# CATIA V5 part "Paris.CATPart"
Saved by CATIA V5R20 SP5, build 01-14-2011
Part number: 巴黎圣母院
Bounding box of the stored display mesh (mm): x -142 to 142, y -290 to 12, z 0 to 410
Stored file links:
  E:\180131213何浏楠\Paris.CATPart
  C:\Program Files\Dassault Systemes\B20\intel_a\startup\materials\Catalog.CATMaterial
  C:\Program Files\Dassault Systemes\B20\intel_a\startup\materials\marble_3.jpg
  C:\Program Files\Dassault Systemes\B20\intel_a\startup\materials\brushed_metal2.jpg
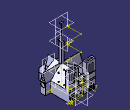
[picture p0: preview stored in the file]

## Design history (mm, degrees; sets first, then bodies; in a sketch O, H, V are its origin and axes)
Body1 (main body)
  Sketch1 on xy-plane, origin (0, 0, 0), H (1, 0, 0), V (0, 1, 0)
    line L1 (-100, -20) -> (100, -20)
    line L2 (100, -20) -> (100, 10)
    line L3 (100, 10) -> (-100, 10)
    line L4 (-100, 10) -> (-100, -20)
    horizontal: L1 H, L3 H
    vertical: L2 V, L4 V
  Pad1: profile Sketch1, direction (0, 0, 1), length 80
  Sketch2 on xy-plane, origin (0, 0, 0), H (1, 0, 0), V (0, 1, 0)
    line L1 (-100, 10) -> (-30, 10)
    line L2 (-30, 10) -> (-30, -20)
    line L3 (-30, -20) -> (-100, -20)
    line L4 (-100, -20) -> (-100, 10)
    point P5 (30, 10)
    line L5 (30, 10) -> (100, 10)
    line L6 (100, 10) -> (100, -20)
    line L7 (100, -20) -> (30, -20)
    line L8 (30, -20) -> (30, 10)
    horizontal: L1 H, L3 H, L5 H, L7 H
    vertical: L2 V, L4 V, L6 V, L8 V
    coincidence: P5 L1
  Pad2: profile Sketch2, direction (0, 0, 1), length 200
  Plane1: type Offset, RefPlane xy-plane, Offset 80
  Sketch3 on Plane1, origin (0, 0, 80), H (1, 0, 0), V (0, 1, 0)
    line L1 (-20, 0) -> (20, 0)
    point P1 (-20, 0)
    coincidence: P1 H
    horizontal: L1 H
  Plane2: type Angle, RefPlane Plane1, Direction Sketch3, Angle 90
  Sketch4 on Plane2, origin (0, 0, 0), H (1, 0, 0), V (0, 0, 1)
    line L1 (-100, 80) -> (100, 80)
    line L2 (100, 80) -> (100, 0)
    line L3 (100, 0) -> (-100, 0)
    line L4 (-100, 0) -> (-100, 80)
    horizontal: L1 H, L3 H
    vertical: L2 V, L4 V
  Pad3: profile Sketch4, direction (0, -1, 0), length 200
  Plane3: type Offset, RefPlane Plane2, Offset 150
  Sketch5 on Plane3, origin (0, -150, 0), H (1, 0, 0), V (0, 0, 1)
    line L1 (-20, 80) -> (20, 80)
    horizontal: L1 H
  Plane4: type Angle, RefPlane Plane3, Direction Sketch5, Angle 90
  Plane5: type Offset, RefPlane Plane4, Offset 80
  Sketch6 on Plane4, origin (0, 0, 80), H (1, 0, 0), V (0, -1, 0)
    point P1 (0, 150)
    line L1 (10, 160) -> (10, 140)
    line L2 (10, 140) -> (-10, 140)
    line L3 (-10, 140) -> (-10, 160)
    line L4 (-10, 160) -> (10, 160)
    coincidence: P1 V
    vertical: L1 V, L3 V
    horizontal: L2 H, L4 H
    equidistance: L1 L3 P1, L2 L4 P1
  Pad4: profile Sketch6, direction (0, 0, 1), length 200
  Sketch7 on Plane2, origin (0, 0, 0), H (1, 0, 0), V (0, 0, 1)
    line L1 (-100, 80) -> (0, 140)
    line L2 (0, 140) -> (100, 80)
    line L3 (-100, 80) -> (100, 80)
    horizontal: L3 H
  Pad5: profile Sketch7, direction (0, -1, 0), length 200
  Plane6: type Offset, RefPlane Plane5, Offset 280, reversed
  Sketch8 on Plane5, origin (0, 0, 0), H (1, 0, 0), V (0, -1, 0)
    line L1 (-100, 170) -> (-140, 170)
    line L2 (-140, 170) -> (-140, 130)
    line L3 (-140, 130) -> (-100, 130)
    line L4 (-100, 130) -> (-100, 170)
    point P5 (100, 170)
    line L5 (100, 170) -> (140, 170)
    line L6 (140, 170) -> (140, 130)
    line L7 (140, 130) -> (100, 130)
    line L8 (100, 130) -> (100, 170)
    point P7 (140, 130)
    horizontal: L1 H, L3 H, L5 H, L7 H
    vertical: L2 V, L4 V, L6 V, L8 V
    coincidence: P5 L1, P7 L3
  Pad6: profile Sketch8, direction (0, 0, 1), length 80
  Sketch9 on Plane5, origin (0, 0, 0), H (1, 0, 0), V (0, -1, 0)
    line L1 (0, 170) -> (0, 130)
    point P1 (0, 170)
    coincidence: P1 V
    vertical: L1 V
  Plane7: type Angle, RefPlane Plane5, Direction Sketch9, Angle 90
  Plane8: type Offset, RefPlane Plane7, Offset 140
  Sketch10 on Plane8, origin (-140, 0, 0), H (0, -1, 0), V (0, 0, 1)
    line L1 (130, 80) -> (150, 140)
    line L2 (150, 140) -> (170, 80)
    line L3 (130, 80) -> (170, 80)
    horizontal: L3 H
  Pad7: profile Sketch10, direction (1, 0, 0), length 280
  Sketch11 on Plane5, origin (0, 0, 0), H (1, 0, 0), V (0, -1, 0)
    line L1 (-20, 200) -> (20, 200)
    line L2 (20, 200) -> (20, 250)
    line L3 (-20, 250) -> (-20, 200)
    arc A1 centre (0, 250) radius 20 from (20, 250) to (-20, 250) ccw
    horizontal: L1 H
    vertical: L2 V, L3 V
    tangency: A1 L2
  Pad8: profile Sketch11, direction (0, 0, 1), length 80
  Sketch12 on Plane3, origin (0, -150, 0), H (1, 0, 0), V (0, 0, 1)
    line L1 (-20, 80) -> (0, 140)
    line L2 (0, 140) -> (20, 80)
    line L3 (-20, 80) -> (20, 80)
    horizontal: L3 H
  Pad9: profile Sketch12, direction (0, -1, 0), length 100
  Plane9: type Offset, RefPlane Plane3, Offset 100
  Sketch13 on Plane9, origin (0, -250, 0), H (1, 0, 0), V (0, 0, 1)
    point P1 (0, 140)
    line L1 (0, 140) -> (-20.024, 80.008)
    line L2 (-20.024, 80.008) -> (-0.9799, 80.008)
    line L3 (-0.9799, 80.008) -> (0, 140)
    axis line L4 (0, 145.4942) -> (0, 57.6388)
    point P4 (0, 145.4942)
    length L1 = 63.2456
    length L3 = 60
    coincidence: P1 V, P4 V
    horizontal: L2 H
    vertical: L4 V
  Shaft1: profile Sketch13, axis Sketch13.L4, angle 180
  Sketch14 on Plane6, origin (0, 0, 280), H (1, 0, 0), V (0, -1, 0)
    line L1 (0, 129.2513) -> (0, 170.6804)
    point P1 (0, 129.2513)
    coincidence: P1 V
    vertical: L1 V
  Plane10: type Angle, RefPlane Plane6, Direction Sketch14, Angle 90
  Sketch15 on Plane10, origin (0, 0, 0), H (0, 1, 0), V (0, 0, 1)
    line L1 (-150, 280) -> (-140, 280)
    line L2 (-140, 280) -> (-150, 400)
    line L3 (-150, 400) -> (-150, 280)
    horizontal: L1 H
    vertical: L3 V
  Shaft2: profile Sketch15, axis Sketch15.L3, angle 360
  Plane11: type Offset, RefPlane Plane2, Offset 10, reversed
  Sketch16 on Plane11, origin (0, 10, 0), H (1, 0, 0), V (0, 0, 1)
    line L1 (80, 120) -> (70, 120)
    line L2 (70, 120) -> (70, 180)
    line L3 (70, 180) -> (80, 180)
    line L4 (80, 180) -> (80, 120)
    point P5 (60, 120)
    line L5 (60, 120) -> (50, 120)
    line L6 (50, 120) -> (50, 180)
    line L7 (50, 180) -> (60, 180)
    line L8 (60, 180) -> (60, 120)
    point P7 (50, 180)
    line L9 (-50, 120) -> (-60, 120)
    line L10 (-60, 120) -> (-60, 180)
    line L11 (-60, 180) -> (-50, 180)
    line L12 (-50, 180) -> (-50, 120)
    point P11 (-60, 180)
    point P13 (-70, 120)
    line L13 (-70, 120) -> (-80, 120)
    line L14 (-80, 120) -> (-80, 180)
    line L15 (-80, 180) -> (-70, 180)
    line L16 (-70, 180) -> (-70, 120)
    point P15 (-80, 180)
    horizontal: L1 H, L3 H, L5 H, L7 H, L9 H, L11 H, L13 H, L15 H
    vertical: L2 V, L4 V, L6 V, L8 V, L10 V, L12 V, L14 V, L16 V
    coincidence: P5 L1, P7 L3, P11 L3, P13 L1, P15 L3
  Pocket1: profile Sketch16, direction (0, -1, 0), length 10
  Sketch17 on Plane11, origin (0, 10, 0), H (1, 0, 0), V (0, 0, 1)
    line L1 (100, 80) -> (-100, 80)
    line L2 (-100, 80) -> (-100, 70)
    line L3 (-100, 70) -> (100, 70)
    line L4 (100, 70) -> (100, 80)
    horizontal: L1 H, L3 H
    vertical: L2 V, L4 V
  Pad10: profile Sketch17, direction (0, 1, 0), length 2
  Sketch18 on Plane11, origin (0, 10, 0), H (1, 0, 0), V (0, 0, 1)
    point P1 (90, 0)
    line L1 (90, 0) -> (90, 30)
    point P2 (90, 30)
    point P3 (50, 30)
    line L2 (50, 30) -> (50, 0)
    line L3 (50, 0) -> (90, 0)
    spline S1 through (90, 30) (70, 50) (50, 30)
    point P5 (40, 0)
    line L4 (40, 0) -> (-40, 0)
    line L5 (-40, 0) -> (-40, 40)
    line L6 (40, 40) -> (40, 0)
    point P7 (-40, 40)
    point P8 (40, 40)
    spline S2 through (40, 40) (0, 60) (-40, 40)
    line L7 (-50, 0) -> (-90, 0)
    line L8 (-90, 0) -> (-90, 30)
    line L9 (-50, 30) -> (-50, 0)
    point P11 (-90, 30)
    point P12 (-50, 30)
    spline S3 through (-50, 30) (-70, 50) (-90, 30)
    point P13 (90, 30)
    point P14 (50, 30)
    point P15 (40, 40)
    point P16 (0, 60)
    point P17 (-40, 40)
    point P18 (-50, 30)
    point P19 (-90, 30)
    coincidence: P1 H, P13 P2, P14 P3, P5 H, P15 P8, P16 V, P17 P7, P18 P12, P19 P11
    vertical: L1 V, L2 V, L5 V, L6 V, L8 V, L9 V
    horizontal: L3 H, L4 H, L7 H
  Pocket2: profile Sketch18, direction (0, -1, 0), length 5
  Sketch19 on Plane11, origin (0, 10, 0), H (1, 0, 0), V (0, 0, 1)
    line L1 (13.6707, 40) -> (5, 40)
    line L2 (5, 40) -> (5, 0)
    line L3 (5, 0) -> (13.6707, 0)
    line L4 (13.6707, 0) -> (13.6707, 40)
    point P5 (-5, 40)
    line L5 (-5, 40) -> (-14.8635, 40)
    line L6 (-14.8635, 40) -> (-14.8635, 0)
    line L7 (-14.8635, 0) -> (-5, 0)
    line L8 (-5, 0) -> (-5, 40)
    distance L2 V = 5
    length L4 = 40
    distance L3 H = 0
    length L6 = 40
    distance V L8 = 5
    horizontal: L1 H, L3 H, L5 H, L7 H
    vertical: L2 V, L4 V, L6 V, L8 V
    coincidence: P5 L1
  Pocket3: profile Sketch19, direction (0, -1, 0), length 15
  Sketch20 on zx-plane, origin (0, 0, 0), H (-1, 0, 0), V (0, 0, 1)
    construction line L1 (-70, 40) -> (-70, -30)
    axis line L2 (70, 40) -> (70, -30)
    line L3 (-80, 30) -> (-73, 30)
    line L4 (-73, 30) -> (-73, 0)
    line L5 (-73, 0) -> (-80, 0)
    line L6 (-80, 0) -> (-80, 30)
    point P7 (-73, 0)
    point P9 (-67, 30)
    line L7 (-67, 30) -> (-60, 30)
    line L8 (-60, 30) -> (-60, 0)
    line L9 (-60, 0) -> (-67, 0)
    line L10 (-67, 0) -> (-67, 30)
    point P11 (-60, 0)
    point P13 (60, 30)
    line L11 (60, 30) -> (67, 30)
    line L12 (67, 30) -> (67, 0)
    line L13 (67, 0) -> (60, 0)
    line L14 (60, 0) -> (60, 30)
    point P15 (67, 0)
    point P17 (80, 30)
    line L15 (80, 30) -> (73, 30)
    line L16 (73, 30) -> (73, 0)
    line L17 (73, 0) -> (80, 0)
    line L18 (80, 0) -> (80, 30)
    point P19 (73, 0)
    distance L1 L4 = 3
    length L3 = 7
    length L9 = 7
    distance L10 L1 = 3
    distance L12 L2 = 3
    length L13 = 7
    length L17 = 7
    distance L18 L2 = 10
    vertical: L1 V, L2 V, L4 V, L6 V, L8 V, L10 V, L12 V, L14 V, L16 V, L18 V
    horizontal: L3 H, L5 H, L7 H, L9 H, L11 H, L13 H, L15 H, L17 H
    coincidence: P7 H, P9 L3, P11 H, P13 L3, P15 H, P17 L3, P19 H
  Pocket4: profile Sketch20, direction (0, -1, 0), length 6, mirrored extent
  Sketch21 on Plane11, origin (0, 10, 0), H (1, 0, 0), V (0, 0, 1)
    axis line L1 (100, 80.5911) -> (-100, 80.5911)
    horizontal: L1 H
  Sketch22 on face of Pad2, origin (0, 10, 0), H (-1, 0, 0), V (0, 0, 1)
    line L1 (-93.8519, 119) -> (-36.8149, 119)
    line L2 (-36.8149, 119) -> (-36.8149, 118)
    line L3 (-36.8149, 118) -> (-93.8519, 118)
    line L4 (-93.8519, 118) -> (-93.8519, 119)
    reference projected line E1 (-100, 80) -> (100, 80) from edge [end face of Pad10 | face of Pad10 from Sketch17.L1]
    point P5 (36.1818, 118)
    line L5 (36.1818, 118) -> (93.7227, 118)
    line L6 (93.7227, 118) -> (93.7227, 119)
    line L7 (93.7227, 119) -> (36.1818, 119)
    line L8 (36.1818, 119) -> (36.1818, 118)
    point P7 (93.7227, 119)
    distance L1 E1 = 39
    length L2 = 1
    horizontal: L1 H, L3 H, L5 H, L7 H
    vertical: L2 V, L4 V, L6 V, L8 V
    coincidence: P5 L3, P7 L1
  Pad11: profile Sketch22, direction (0, 1, 0), length 2
  Sketch23 on start face of Pad5, origin (0, 0, 0), H (-1, 0, 0), V (0, 0, 1)
    circle A1 centre (0, 110) radius 21.5
    radius A1 = 21.5
  Pocket5: profile Sketch23, direction (0, -1, 0), length 2
  Sketch24 on face of Pad7, origin (140, 0, 0), H (0, 1, 0), V (0, 0, 1)
    circle A1 centre (-150, 60) radius 15
    reference intersected line E2 through (0, 80) direction (1, 0) from Plane4
    radius A1 = 15
    distance E2 A1 = 5
  Pocket6: profile Sketch24, direction (-1, 0, 0), length 2
  Sketch25 on face of Pad7, origin (140, 0, 0), H (0, 1, 0), V (0, 0, 1)
    line L1 (-170, 80) -> (-130, 80)
    line L2 (-130, 80) -> (-130, 78)
    line L3 (-130, 78) -> (-170, 78)
    line L4 (-170, 78) -> (-170, 80)
    point P2 (-130, 80)
    reference intersected line E1 through (-150, 0) direction (0, -1) from Plane3
    length L2 = 2
    distance E1 P2 = 20
    horizontal: L1 H, L3 H
    vertical: L2 V, L4 V
  Pad12: profile Sketch25, direction (1, 0, 0), length 2
  Sketch26 on face of Pad7, origin (140, 0, 0), H (0, 1, 0), V (0, 0, 1)
    circle A1 centre (-150, 100) radius 10
  Pocket7: profile Sketch26, direction (-1, 0, 0), length 2
  Sketch27 on face of Pad7, origin (-140, 0, 0), H (0, -1, 0), V (0, 0, 1)
    circle A1 centre (150, 60) radius 15
    point P2 (130, 80)
    line L1 (130, 80) -> (170, 80)
    line L2 (170, 80) -> (170, 78)
    line L3 (170, 78) -> (130, 78)
    line L4 (130, 78) -> (130, 80)
    reference intersected line E1 through (150, 0) direction (0, 1) from Plane3
    radius A1 = 15
    length L2 = 2
    distance E1 P2 = 20
    horizontal: L1 H, L3 H
    vertical: L2 V, L4 V
  Pocket8: profile Sketch27, direction (1, 0, 0), length 2
  Pad13: profile Sketch27, direction (-1, 0, 0), length 2
  Sketch28 on face of Pad7, origin (-140, 0, 0), H (0, -1, 0), V (0, 0, 1)
    circle A1 centre (150, 100) radius 10
  Pocket9: profile Sketch28, direction (1, 0, 0), length 2
  Plane12: type Offset, RefPlane Plane6, Offset 120, reversed
  Sketch29 on Plane12, origin (0, 0, 400), H (1, 0, 0), V (0, -1, 0)
    circle A1 centre (0, 150) radius 0.5
    point P1 (0, 150)
    radius A1 = 0.5
    coincidence: P1 V
  Pad14: profile Sketch29, direction (0, 0, 1), length 10, mirrored extent
  Sketch30 on Plane12, origin (0, 0, 400), H (1, 0, 0), V (0, -1, 0)
    line L1 (-10, 150) -> (10, 150)
    horizontal: L1 H
  Plane13: type Angle, RefPlane Plane12, Direction Sketch30, Angle 90
  Sketch31 on end face of Pad2, origin (0, 0, 200), H (1, 0, 0), V (0, 1, 0)
    point P1 (40, 0)
    line L1 (40, 0) -> (90, 0)
    line L2 (90, 0) -> (90, -10)
    line L3 (90, -10) -> (40, -10)
    line L4 (40, -10) -> (40, 0)
    point P5 (-90, 0)
    line L5 (-90, 0) -> (-40, 0)
    line L6 (-40, 0) -> (-40, -10)
    line L7 (-40, -10) -> (-90, -10)
    line L8 (-90, -10) -> (-90, 0)
    point P7 (-40, -10)
    coincidence: P1 H, P5 H, P7 L3
    horizontal: L1 H, L3 H, L5 H, L7 H
    vertical: L2 V, L4 V, L6 V, L8 V
  Pocket10: profile Sketch31, direction (0, 0, -1), length 10
  Sketch32 on face of Pad8, origin (0, 0, 0), H (1, 0, 0), V (0, -1, 0)
    line L1 (-60, 200) -> (-60, 260)
    line L2 (-60, 260) -> (-30, 290)
    line L3 (-30, 290) -> (30, 290)
    line L4 (30, 290) -> (60, 260)
    line L5 (60, 260) -> (60, 200)
    line L6 (60, 200) -> (-60, 200)
    vertical: L1 V, L5 V
    horizontal: L3 H, L6 H
    perpendicularity: L4 L2
  Pad15: profile Sketch32, direction (0, 0, 1), length 50
  Sketch33 on face of Pad15 from Sketch32.L3, origin (0, -290, 0), H (1, 0, 0), V (0, 0, 1)
    line L1 (20, 20) -> (20, 0)
    line L2 (20, 0) -> (10, 0)
    line L3 (10, 0) -> (10, 20)
    line L4 (-10, 20) -> (-10, 0)
    line L5 (-10, 0) -> (-20, 0)
    line L6 (-20, 0) -> (-20, 20)
    point P9 (-10, 39.7196)
    point P10 (-20, 30)
    arc A1 centre (-15, 20) radius 5 from (-20, 20) to (-10, 20) cw
    arc A2 centre (15, 20) radius 5 from (10, 20) to (20, 20) cw
    horizontal: L2 H, L5 H
    vertical: L1 V, L3 V, L4 V, L6 V
    coincidence: P9 L4, P10 L6
    tangency: A1 L6, A2 L1
  Pocket11: profile Sketch33, direction (0, 1, 0), length 20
